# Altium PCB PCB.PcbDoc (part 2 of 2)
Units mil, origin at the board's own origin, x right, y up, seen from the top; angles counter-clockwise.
Board outline 3920 x 1470 mil, 2 copper layers (Top Layer, Bottom Layer), stack 60.433 mil thick; 97 components, 79 nets, 353 pads, 374 vias.
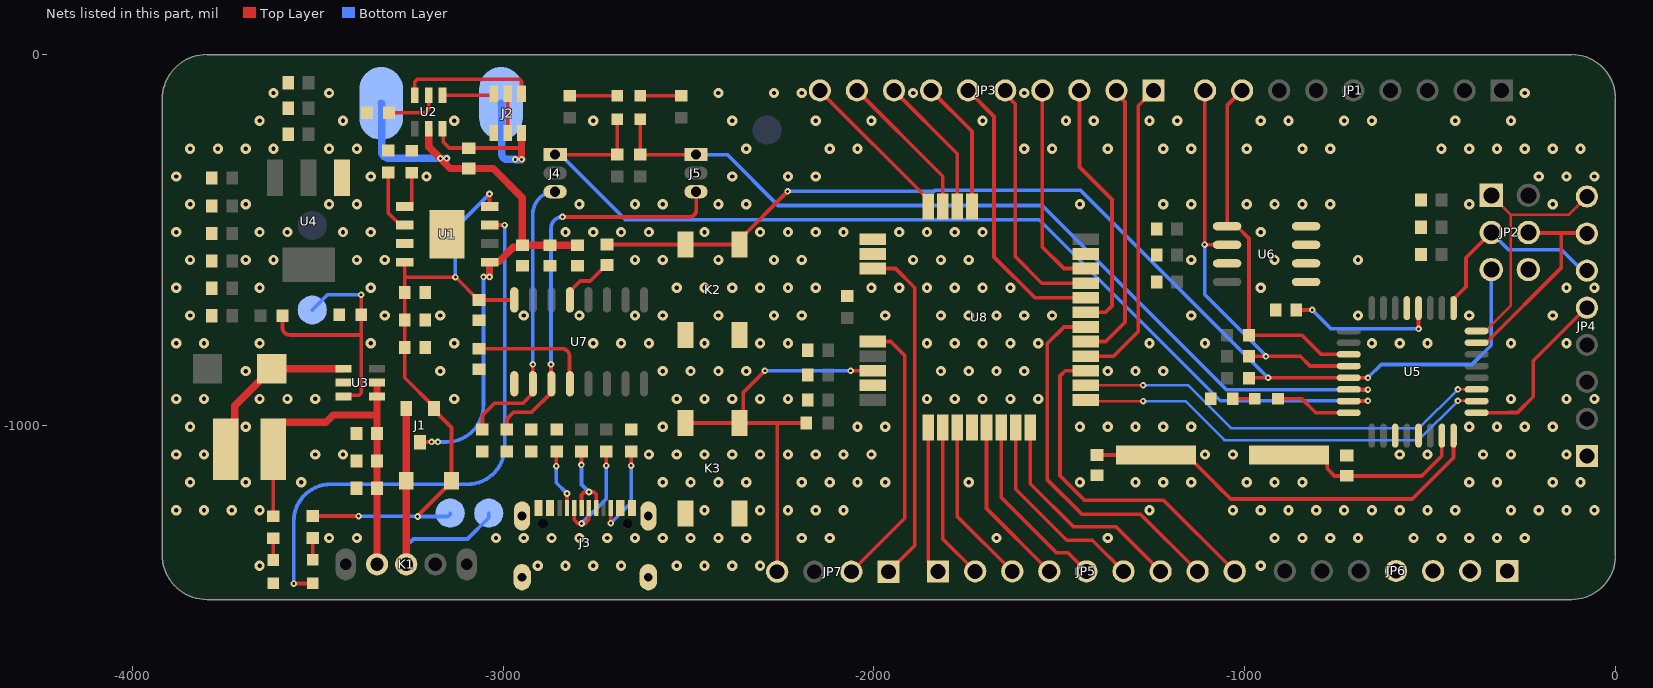
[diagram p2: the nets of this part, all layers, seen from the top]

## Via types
v1: diameter 27.56, hole 11.81, Top Layer to Bottom Layer, tented both sides, 319 vias
v2: diameter 17.72, hole 7.87, Top Layer to Bottom Layer, tented both sides, 55 vias

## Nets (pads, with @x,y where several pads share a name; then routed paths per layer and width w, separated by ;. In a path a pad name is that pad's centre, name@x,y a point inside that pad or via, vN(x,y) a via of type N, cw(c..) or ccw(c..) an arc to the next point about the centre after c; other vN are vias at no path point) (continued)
GND: C1.2 C2.2 C3.2 C4.2 C5.2 C6.2 C8.2 C9.2 C10.2 C11.2 C12.2 C13.2 C14.2 C15.2 C16.2 C17.2 C18.2 C19.2 C20.2 C21.2 C23.2 C24.2 C25.2 C26.2 C27.2 C28.2 C30.2 C31.2 C32.2 C33.2 C34.2 C35.2 D3.1 J2.1 J3.1 J3.12 J3.13 J3.14 JP2.4 JP4.1 JP6.1 JP6.2 JP6.3 JP6.4 K2.1 K2.3 K3.1 K3.3 R2.1 R3.1 R4.1 R5.1 R8.1 R9.2 R10.2 R14.2 R23.1 U1.3 U1.9 U3.2 U4.1 U5.3 U5.5 U5.21 U6.1 U6.2 U6.3 U6.4 U6.7 U7.1 U8.11 U8.17 U8.18 U8.23 U8.28
  other v1: -3657,-1378.95 -2907,-1378.95 -2832,-1378.95 -2757,-1378.95 -2682,-1378.95 -2532,-1378.95 -2457,-1378.95 -2382,-1378.95 -2307,-1378.95 -957,-1378.95 -3469.5,-1303.95 -3394.5,-1303.95 -3019.5,-1303.95 -2944.5,-1303.95 -2869.5,-1303.95 -2794.5,-1303.95 -2719.5,-1303.95 -2644.5,-1303.95 -2569.5,-1303.95 -2494.5,-1303.95 -2419.5,-1303.95 -2344.5,-1303.95 -2194.5,-1303.95 -2119.5,-1303.95 -1669.5,-1303.95 -1369.5,-1303.95 -919.5,-1303.95 -844.5,-1303.95 -769.5,-1303.95 -694.5,-1303.95 -544.5,-1303.95 -469.5,-1303.95 -394.5,-1303.95 -319.5,-1303.95 -244.5,-1303.95 -3882,-1228.95 -3807,-1228.95 -3732,-1228.95 -3657,-1228.95 -2457,-1228.95 -2307,-1228.95 -2232,-1228.95 -2157,-1228.95 -2082,-1228.95 -1257,-1228.95 -1032,-1228.95 -957,-1228.95 -882,-1228.95 -807,-1228.95 -732,-1228.95 -657,-1228.95 -582,-1228.95 -507,-1228.95 -432,-1228.95 -282,-1228.95 -207,-1228.95 -132,-1228.95 -57,-1228.95 -3844.5,-1153.95 -3694.5,-1153.95 -3544.5,-1153.95 -2569.5,-1153.95 -2494.5,-1153.95 -2419.5,-1153.95 -2344.5,-1153.95 -2194.5,-1153.95 -2119.5,-1153.95 -2044.5,-1153.95 -1969.5,-1153.95 -1744.5,-1153.95 -1444.5,-1153.95 -1294.5,-1153.95 -1219.5,-1153.95 -1144.5,-1153.95 -994.5,-1153.95 -919.5,-1153.95 -844.5,-1153.95 -394.5,-1153.95 -319.5,-1153.95 -169.5,-1153.95 -94.5,-1153.95 -3882,-1078.95 -3807,-1078.95 -3507,-1078.95 -3432,-1078.95 -2607,-1078.95 -2532,-1078.95 -2457,-1078.95 -2382,-1078.95 -2307,-1078.95 -2232,-1078.95 -2157,-1078.95 -2082,-1078.95 -2007,-1078.95 -1107,-1078.95 -1032,-1078.95 -582,-1078.95 -507,-1078.95 -357,-1078.95 -282,-1078.95 -132,-1078.95 -3844.5,-1003.95 -3694.5,-1003.95 -2569.5,-1003.95 -2044.5,-1003.95 -1969.5,-1003.95 -1444.5,-1003.95 -1369.5,-1003.95 -1294.5,-1003.95 -1219.5,-1003.95 -1144.5,-1003.95 -394.5,-1003.95 -319.5,-1003.95 -244.5,-1003.95 -169.5,-1003.95 -3882,-928.95 -3807,-928.95 -3657,-928.95 -3582,-928.95 -3507,-928.95 -3132,-928.95 -2532,-928.95 -2457,-928.95 -2382,-928.95 -2307,-928.95 -2232,-928.95 -1857,-928.95 -1782,-928.95 -1707,-928.95 -1632,-928.95 -1557,-928.95 -282,-928.95 -132,-928.95 -57,-928.95 -3694.5,-853.95 -3169.5,-853.95 -2569.5,-853.95 -2494.5,-853.95 -2419.5,-853.95 -2344.5,-853.95 -1819.5,-853.95 -1744.5,-853.95 -1669.5,-853.95 -1594.5,-853.95 -1369.5,-853.95 -1294.5,-853.95 -1219.5,-853.95 -3882,-778.95 -3807,-778.95 -3657,-778.95 -3357,-778.95 -3132,-778.95 -2757,-778.95 -2682,-778.95 -2607,-778.95 -2457,-778.95 -2307,-778.95 -2232,-778.95 -1857,-778.95 -1782,-778.95 -1707,-778.95 -1632,-778.95 -1557,-778.95 -1257,-778.95 -1107,-778.95 -657,-778.95 -582,-778.95 -507,-778.95 -282,-778.95 -132,-778.95 -3844.5,-703.95 -3319.5,-703.95 -3169.5,-703.95 -2944.5,-703.95 -2794.5,-703.95 -2644.5,-703.95 -2569.5,-703.95 -2419.5,-703.95 -2269.5,-703.95 -2194.5,-703.95 -1969.5,-703.95 -1819.5,-703.95 -1744.5,-703.95 -1669.5,-703.95 -1594.5,-703.95 -1519.5,-703.95 -1144.5,-703.95 -694.5,-703.95 -394.5,-703.95 -169.5,-703.95 -3882,-628.95 -3657,-628.95 -3357,-628.95 -2532,-628.95 -2457,-628.95 -2382,-628.95 -2307,-628.95 -2232,-628.95 -2157,-628.95 -2007,-628.95 -1932,-628.95 -1857,-628.95 -1782,-628.95 -1707,-628.95 -1632,-628.95 -957,-628.95 -132,-628.95 -57,-628.95 -3844.5,-553.95 -3694.5,-553.95 -3619.5,-553.95 -3394.5,-553.95 -3319.5,-553.95 -2644.5,-553.95 -2569.5,-553.95 -2419.5,-553.95 -2269.5,-553.95 -2194.5,-553.95 -1894.5,-553.95 -1819.5,-553.95 -1744.5,-553.95 -1144.5,-553.95 -919.5,-553.95 -694.5,-553.95 -3882,-478.95 -3657,-478.95 -3582,-478.95 -3432,-478.95 -3357,-478.95 -2832,-478.95 -2757,-478.95 -2682,-478.95 -2607,-478.95 -2457,-478.95 -2307,-478.95 -2232,-478.95 -2157,-478.95 -2082,-478.95 -1932,-478.95 -1857,-478.95 -1782,-478.95 -1707,-478.95 -957,-478.95 -3844.5,-403.95 -3694.5,-403.95 -3469.5,-403.95 -3394.5,-403.95 -2794.5,-403.95 -2644.5,-403.95 -2569.5,-403.95 -2419.5,-403.95 -2344.5,-403.95 -1444.5,-403.95 -1219.5,-403.95 -1144.5,-403.95 -994.5,-403.95 -919.5,-403.95 -844.5,-403.95 -769.5,-403.95 -394.5,-403.95 -169.5,-403.95 -3882,-328.95 -3357,-328.95 -3207,-328.95 -2382,-328.95 -2232,-328.95 -2157,-328.95 -207,-328.95 -132,-328.95 -57,-328.95 -3844.5,-253.95 -3769.5,-253.95 -3694.5,-253.95 -3619.5,-253.95 -3469.5,-253.95 -3394.5,-253.95 -2344.5,-253.95 -2119.5,-253.95 -2044.5,-253.95 -1594.5,-253.95 -1519.5,-253.95 -1369.5,-253.95 -1219.5,-253.95 -1144.5,-253.95 -994.5,-253.95 -844.5,-253.95 -769.5,-253.95 -469.5,-253.95 -394.5,-253.95 -319.5,-253.95 -244.5,-253.95 -169.5,-253.95 -94.5,-253.95 -3657,-178.95 -3432,-178.95 -3132,-178.95 -2757,-178.95 -2382,-178.95 -2157,-178.95 -2007,-178.95 -1707,-178.95 -1482,-178.95 -1407,-178.95 -1257,-178.95 -1182,-178.95 -957,-178.95 -882,-178.95 -732,-178.95 -657,-178.95 -432,-178.95 -282,-178.95 -3619.5,-103.95 -3469.5,-103.95 -2419.5,-103.95 -2269.5,-103.95 -2194.5,-103.95 -1894.5,-103.95 -1594.5,-103.95 -244.5,-103.95
MISO: JP2.1 JP4.8 U5.16 | length 665.3
  Top Layer w7: U5.16@-374.5,-745.76 -350.88,-745.76 -283,-677.89 -283,-432 ; JP2.1@-335,-380 -283,-432 ; JP4.8@-77,-383 -126,-432 -283,-432
MOSI: JP2.5 JP4.7 U5.15 | length 564.7
  Top Layer w10: U5.15@-374.5,-777.26 -348.88,-777.26 -146,-574.38 -146,-481.5 ; JP2.5@-235,-480 -233.5,-481.5 -146,-481.5 ; JP4.7@-77,-483 -78.5,-481.5 -146,-481.5
NetC7_2: C7.2 J2.3 SP2.1 U2.6 | length 519.2
  Top Layer w10: U2.6@-3163.6,-200.24 -3161.66,-202.17 -3161.66,-236.34 -3145.56,-252.44 C7.2@-3093,-252.44 -2957.44,-252.44 ; v2@-2967.78,-283.28 v2(-2967.5,-283) ; v2@-2950.6,-283 v2(-2950.5,-283) v2@-2950,-283
  Top Layer w20: v2@-2950.6,-283 J2.3@-2950.6,-212.15
  Bottom Layer w20: SP2.1@-3006,-132 cw(c-3006,-134) -3004,-134 -3004,-267 ccw(c-2988,-267) -2988,-283 v2(-2967.5,-283) -2966.5,-284 -2951.5,-284 v2(-2950.5,-283)
NetC20_1: C20.1 C22.2 U5.7 | length 522.2
  Top Layer w10: C22.2@-880.75,-1080 -798.07,-1080 -777.48,-1100.59 -777.48,-1116.8 -757.72,-1136.56 C20.1@-725,-1136.56 -522.56,-1136.56 -468.26,-1082.26 U5.7@-468.26,-1028
NetC21_1: C21.1 C22.1 U5.8 | length 1116.6
  Top Layer w10: C21.1@-1398,-1080 C22.1@-1239.25,-1080 -1156.57,-1080 -1076,-1160.57 -1076,-1161 -1038,-1199 -548,-1199 -436.76,-1087.76 U5.8@-436.76,-1028
NetC23_1: C23.1 U5.20 | length 407.3
  Top Layer w10: C23.1@-861.44,-689 v2(-818,-689) ; U5.20@-531.25,-684 -531.2,-684.06 -531.2,-739.8 v2(-531.14,-739.86)
  Bottom Layer w10: v2(-818,-689) -767.14,-739.86 v2(-531.14,-739.86)
NetC27_1: C27.1 U7.4 | length 330.4
  Top Layer w10: C27.1@-3065,-793.44 -2841.56,-793.44 cw(c-2841.56,-814) -2821,-814 -2821,-887.09 ccw(c-2820,-887.09) U7.4@-2820,-888.09
NetC29_1: C29.1 U7.13 | length 152.7
  Top Layer w10: U7.13@-2820,-661.91 -2820,-638.58 -2792.42,-611 -2765.41,-611 -2721.97,-567.56 C29.1@-2720,-567.56
NetD1_1: D1.1 U1.7 | length 1543.1
  Top Layer w10: v2(-3565,-1427) -3514.46,-1427 ccw(c-3514.46,-1425.94) D1.1@-3513.4,-1425.94 ; U1.7@-3036.75,-460 v2(-2996,-460)
  Bottom Layer w10: v2(-3565,-1427) -3565,-1259 cw(c-3465,-1259) -3465,-1159 -3096,-1159 ccw(c-3096,-1059) -2996,-1059 v2(-2996,-460)
NetD1_2: D1.2 R1.2 | length 58.9
  Top Layer w10: D1.2@-3513.68,-1362.99 R1.2@-3513.68,-1304.12
NetD2_2: D2.2 L1.2 U3.1 | length 462.2
  Top Layer w20: L1.2@-3748.1,-1065 -3723.65,-1040.55 -3723.65,-946.86 D2.2@-3624.38,-847.6 U3.1@-3430.79,-847.6
NetD3_2: D3.2 R7.2 | length 58.9
  Top Layer w10: D3.2@-3620.14,-1363.52 R7.2@-3620.14,-1304.66
NetD5_1: D5.1 R14.1 | length 58.9
  Top Layer w10: R14.1@-1032.07,-928.25 -973.34,-928.25 D5.1@-973.2,-928.38
NetD6_2: D6.2 R16.2 | length 110.3
  Top Layer w10: D6.2@-2630.28,-111.34 R16.2@-2520,-111.34
NetD7_2: D7.2 R17.2 | length 127.3
  Top Layer w10: R17.2@-2820,-111.34 D7.2@-2692.68,-111.34
NetJ2_2: J2.2 J2.5 | length 106.3
  Top Layer w10: J2.2@-2988,-212.15 J2.5@-2988,-105.85
NetJ2_4: J2.4 U2.3 | length 362.5
  Top Layer w10: U2.3@-3238.4,-109.76 -3238.4,-74.4 -3230.4,-66.4 -2956.46,-66.4 -2950.6,-72.26 J2.4@-2950.6,-105.85
NetJ2_6: J2.6 U2.1 | length 139.8
  Top Layer w10: U2.1@-3163.6,-109.76 -3029.32,-109.76 J2.6@-3025.4,-105.85
NetJ3_4: J3.4 R10.1 | length 164.4
  Top Layer w10: v2(-2857,-1110) -2857,-1071.89 R10.1@-2855.98,-1070.88 ; J3.4@-2827.99,-1222.87 v2(-2828,-1184)
  Bottom Layer w10: v2(-2857,-1110) -2857,-1155 v2(-2828,-1184)
NetJ3_5: J3.5 J3.7 R12.1 | length 337.7
  Top Layer w10: J3.5@-2808.31,-1222.87 -2808.31,-1254.69 -2798,-1265 v2(-2788.5,-1265) -2779,-1265 -2768.94,-1254.94 J3.7@-2768.94,-1222.87 ; v2(-2722.03,-1108.85) -2722,-1111 -2721.8,-1110.8 R12.1@-2721.8,-1070.88
  Bottom Layer w10: v2(-2788.5,-1265) -2722.03,-1198.53 v2(-2722.03,-1108.85)
NetJ3_6: J3.6 J3.8 R11.1 | length 234.4
  Top Layer w10: v2(-2789,-1107) -2788.73,-1106.73 R11.1@-2788.73,-1070.88 ; J3.6@-2788.62,-1222.87 -2788.62,-1187.62 -2781,-1180 v2(-2768.5,-1180) -2756,-1180 -2749.26,-1186.74 J3.8@-2749.26,-1222.87
  Bottom Layer w10: v2(-2789,-1107) -2789,-1159.5 v2(-2768.5,-1180)
NetJ3_10: J3.10 R9.1 | length 257.1
  Top Layer w10: v2(-2710,-1264) -2710,-1261 -2709.89,-1260.89 J3.10@-2709.89,-1222.87 ; v2(-2655,-1109) -2655,-1071.01 R9.1@-2654.87,-1070.88
  Bottom Layer w10: v2(-2710,-1264) -2655,-1209 v2(-2655,-1109)
NetR2_2: R2.2 U1.2 | length 166.7
  Top Layer w10: R2.2@-3309.81,-318.44 -3309.81,-427.75 -3277.56,-460 U1.2@-3265.75,-460
NetR4_2: R4.2 U1.1 | length 106
  Top Layer w10: U1.1@-3265.75,-410 -3253.94,-410 -3247.13,-403.19 -3247.13,-397.46 -3247,-397.33 R4.2@-3247,-318.66
NetR5_2: R5.2 U2.2 | length 148.7
  Top Layer w10: R5.2@-3308.34,-157 -3211,-157 -3201,-147 U2.2@-3201,-109.76
NetR6_1: R6.1 R8.2 TP3.1 U3.3 | length 721.6
  Top Layer w10: R6.1@-3595.34,-704.46 -3595.34,-736.66 ccw(c-3575.66,-736.66) -3575.66,-756.34 -3383,-756.34 ; U3.3@-3430.79,-922.4 -3427.59,-919.2 -3388.86,-919.2 -3383,-913.34 -3383,-756.34 ; v2(-3383,-648) R8.2@-3383,-702 -3383,-756.34
  Bottom Layer w10: TP3.1@-3515,-689 -3474,-648 v2(-3383,-648)
PA0: JP5.4 U8.29 | length 458.2
  Top Layer w10: U8.29@-1696.31,-1005.98 -1696.31,-1224.69 JP5.4@-1527,-1394
PA1: JP5.8 U8.6 | length 997.4
  Top Layer w10: U8.6@-1429.09,-734.78 -1487.77,-734.78 -1533,-780 -1533,-1146 -1439,-1240 -1281,-1240 JP5.8@-1127,-1394
PA8: JP7.1 U8.19 | length 929.7
  Top Layer w10: U8.19@-2002.91,-577.3 -1941.7,-577.3 -1890,-629 -1890,-1324 JP7.1@-1961,-1395
PA9: JP7.2 U8.20 | length 744.2
  Top Layer w10: JP7.2@-2061,-1395 -1917,-1251 -1917,-812 -1954.85,-774.15 U8.20@-2002.91,-774.15
PA10: JP5.1 U8.25 | length 399.1
  Top Layer w10: U8.25@-1853.79,-1005.98 -1853.79,-1367.21 JP5.1@-1827,-1394
PA15: JP5.9 U8.3 | length 921.6
  Top Layer w10: U8.3@-1429.09,-852.89 -1483.89,-852.89 -1498,-867 -1498,-1136 -1432,-1202 -1219,-1202 JP5.9@-1027,-1394
PB2: JP5.2 U8.26 | length 424.2
  Top Layer w10: U8.26@-1814.42,-1005.98 -1814.42,-1306.58 JP5.2@-1727,-1394
PB3: JP5.7 U8.32 | length 600.9
  Top Layer w10: U8.32@-1578.2,-1005.98 -1578.2,-1157.8 -1462,-1274 -1347,-1274 JP5.7@-1227,-1394
PB4: JP5.6 U8.31 | length 548.8
  Top Layer w10: U8.31@-1617.57,-1005.98 -1617.57,-1172.43 -1480,-1310 -1411,-1310 JP5.6@-1327,-1394
PB5: JP5.5 U8.30 | length 501.4
  Top Layer w10: U8.30@-1656.94,-1005.98 -1656.94,-1195.06 -1508,-1344 -1477,-1344 JP5.5@-1427,-1394
PB12: JP5.3 U8.27 | length 449.3
  Top Layer w10: U8.27@-1775.05,-1005.98 -1775.05,-1245.95 JP5.3@-1627,-1394
RESET: C29.2 JP2.3 K2.2 K2.4 R18.1 U5.29 | length 2955.8
  Top Layer w10: C29.2@-2720,-512.44 K2.2@-2507.84,-512.44 K2.4@-2362.16,-512.44 -2362.16,-498.66 -2233,-369.5 v2(-2233,-369) ; R18.1@-988.18,-872.78 -987.15,-871.75 v2(-937,-871.75) U5.29@-719.5,-871.75 -719.25,-872 v2(-668,-872)
  Bottom Layer w10: v2(-2233,-369) -1838.33,-369 -1835.33,-366 -1442.75,-366 v2(-937,-871.75) ; v2(-668,-872) -632,-836 -386.8,-836 -335,-784.2 JP2.3@-335,-580
RESET_RAK3172: JP7.4 K3.2 K3.4 R24.1 U8.22 | length 1172.7
  Top Layer w10: K3.2@-2497.84,-994 K3.4@-2352.16,-994 ; v2(-2294,-853) -2352.16,-911.16 K3.4@-2352.16,-994 ; JP7.4@-2261,-1395 -2261,-995 -2260,-994 ; R24.1@-2182.76,-994 -2260,-994 ; v2(-2063,-853) -2062.89,-852.89 U8.22@-2002.91,-852.89 ; K3.4@-2352.16,-994 -2260,-994
  Bottom Layer w10: v2(-2294,-853) v2(-2063,-853)
RESET_TFT: JP4.5 U5.9 | length 471.6
  Top Layer w10: U5.9@-374.5,-966.24 -289.98,-966.24 -289.25,-965.5 -264.5,-965.5 -221.84,-922.84 -221.84,-825.84 -79,-683 JP4.5@-77,-683
RXD_HV: J5.3 R21.2 U7.3 | length 1091.1
  Top Layer w10: R21.2@-2990,-1011.34 -2990,-983 -2972,-965 -2923.58,-965 -2870,-911.42 U7.3@-2870,-888.09 cw(c-2870,-887.09) -2871,-887.09 v2(-2871,-836) ; v2(-2840,-438) -2498,-438 ccw(c-2498,-419) -2479,-419 -2479,-371 ccw(c-2480,-371) J5.3@-2480,-370
  Bottom Layer w10: v2(-2871,-836) -2871,-469 cw(c-2840,-469) v2(-2840,-438)
RXD_LV: D7.1 J4.1 R20.2 U5.31 | length 2782.1
  Top Layer w10: J4.1@-2860,-270 R20.2@-2692.41,-270 D7.1@-2692.41,-174.29 ; U5.31@-719.5,-934.74 -719.13,-934.37 -668.37,-934.37 v2(-668,-934)
  Bottom Layer w10: J4.1@-2860,-270 -2846.22,-270 -2670.22,-446 -1554,-446 -1066,-934 v2(-668,-934)
RXD_RAK3172: U5.10 U8.1 | length 1143.7
  Top Layer w7: U8.1@-1429.09,-931.62 -1425.72,-935 v2(-1274,-935) ; v2(-425,-934) -424.63,-934.37 -374.87,-934.37 U5.10@-374.5,-934.74
  Bottom Layer w7: v2(-1274,-935) -1159.61,-935 -1054.61,-1040 -531,-1040 v2(-425,-934)
S1_MISO_RAK: JP3.8 U8.14 | length 383.8
  Top Layer w10: JP3.8@-1945.91,-97.02 -1775.06,-267.88 U8.14@-1775.06,-410.02
S1_MOSI_RAK: JP3.7 U8.13 | length 358.7
  Top Layer w10: JP3.7@-1845.91,-97.02 -1735.69,-207.25 U8.13@-1735.69,-410.02
S1_NSS_RAK: JP3.10 U8.16 | length 434
  Top Layer w10: JP3.10@-2145.91,-97.02 -2145.91,-98.22 -1853.8,-390.34 U8.16@-1853.8,-410.02
S1_SCK_RAK: JP3.9 U8.15 | length 408.9
  Top Layer w10: JP3.9@-2045.91,-97.02 -1814.43,-328.51 U8.15@-1814.43,-410.02
SCK: JP2.2 JP4.6 U5.17 | length 546.8
  Top Layer w10: U5.17@-436.76,-684 -436.76,-660.38 -403,-626.61 -403,-548 JP2.2@-335,-480
  Bottom Layer w10: JP2.2@-335,-480 -288,-527 -145,-527 -89,-583 JP4.6@-77,-583
SCL: JP1.9 R13.2 U5.28 U6.6 | length 1127.1
  Top Layer w10: JP1.9@-1107,-97 -1107.5,-97.5 -1107.5,-512.5 v2(-1108,-513) -1107.59,-513.41 U6.6@-1047.5,-513.41 ; R13.2@-988.18,-813.78 -850.22,-813.78 -823.75,-840.25 U5.28@-719.5,-840.25
  Bottom Layer w10: v2(-1108,-513) -1108,-647 -942.76,-812.24 v2(-942.76,-814.27) ; JP1.9@-1107.5,-97.5 JP1.9@-1107,-97
SCL_RAK: JP3.5 U8.9 | length 678.7
  Top Layer w10: JP3.5@-1645.91,-97.02 -1645.91,-106.72 -1619,-133.64 -1619,-545 -1547.34,-616.66 U8.9@-1429.09,-616.66
SDA: JP1.8 R15.2 U5.27 U6.5 | length 1006.8
  Top Layer w10: JP1.8@-1007,-97 -1047.5,-137.5 U6.5@-1047.5,-463.41 -1021.59,-463.41 -988.73,-496.27 -988.73,-756.68 R15.2@-988.18,-757.23 -845.77,-757.23 -794.24,-808.76 U5.27@-719.5,-808.76
SDA_RAK: JP3.4 U8.10 | length 563
  Top Layer w10: JP3.4@-1545.91,-97.02 -1545.91,-519.09 -1487.7,-577.3 U8.10@-1429.09,-577.3
SWCLK_RAK: JP3.6 U8.8 | length 770.4
  Top Layer w10: JP3.6@-1745.91,-97.02 -1676,-166.94 -1676,-546 -1565.97,-656.03 U8.8@-1429.09,-656.03
SWDIO_RAK: JP3.3 U8.7 | length 695.7
  Top Layer w10: JP3.3@-1445.91,-97.02 -1445.91,-303.09 -1358,-391 -1358,-678 -1375.4,-695.41 U8.7@-1429.09,-695.41
"TOGGLE LED": D5.2 U5.32 | length 206.5
  Top Layer w10: D5.2@-910.25,-928.11 -846.89,-928.11 -808.76,-966.24 U5.32@-719.5,-966.24
TXD_HV: J4.3 R19.2 U7.2 | length 776.8
  Top Layer w10: R19.2@-3056,-1011.34 -3056,-973 -3024,-941 -2947.42,-941 -2920,-913.58 U7.2@-2920,-888.09 v2(-2920,-836)
  Bottom Layer w10: v2(-2920,-836) -2920,-430 cw(c-2860,-430) J4.3@-2860,-370
TXD_LV: D6.1 J5.1 R22.2 U5.30 | length 2372.1
  Top Layer w10: D6.1@-2630,-174.29 R22.2@-2630,-270 J5.1@-2480,-270 ; U5.30@-719.5,-903.24 -719.12,-903.62 -668.38,-903.62 v2(-668,-904)
  Bottom Layer w10: J5.1@-2480,-270 -2396,-270 -2259,-407 -1546,-407 -1049,-904 v2(-668,-904)
TXD_RAK3172: U5.11 U8.2 | length 1146.3
  Top Layer w7: U8.2@-1429.09,-892.26 -1274.26,-892.26 v2(-1274,-892) ; v2(-425,-903) -424.88,-903.12 -374.62,-903.12 U5.11@-374.5,-903.24
  Bottom Layer w7: v2(-1274,-892) -1153,-892 -1037,-1008 -530,-1008 v2(-425,-903)
U1_TXD_RAK: JP3.1 U8.4 | length 836.6
  Top Layer w10: U8.4@-1429.09,-813.51 -1353.52,-813.51 -1287,-747 -1287,-138.11 JP3.1@-1245.91,-97.02
U2_RXD_RAK: JP3.2 U8.5 | length 762.2
  Top Layer w10: U8.5@-1429.09,-774.14 -1375.15,-774.14 -1323,-722 -1323,-127.8 -1345.91,-104.89 JP3.2@-1345.91,-97.02
V-BAT: C4.1 C5.1 C6.1 C7.1 J1.3 SP1.1 U1.5 U2.5 | length 1673.3
  Top Layer w10: J1.3@-3224.17,-1045.28 -3193.28,-1045.28 v2(-3193,-1045) ; v2@-3169.75,-280.25 v2(-3169.5,-280)
  Top Layer w20: U2.5@-3201,-200.24 -3201,-249 -3169.75,-280.25 -3142.44,-307.56 C7.1@-3093,-307.56 -3026.44,-307.56 -2948.12,-385.88 C4.1@-2948.12,-514.25 ; v2(-3037,-600) -3037,-560.25 -3034.94,-558.19 -3011.19,-558.19 -2973,-520 -2953.87,-520 C4.1@-2948.12,-514.25 ; C6.1@-2800.07,-514.25 C5.1@-2874.21,-514.25 C4.1@-2948.12,-514.25
  Bottom Layer w10: v2(-3193,-1045) -3192,-1046 -3177,-1046 v2(-3176,-1045) -3153,-1045 ccw(c-3153,-945) -3053,-945 v2(-3053,-600)
  Bottom Layer w20: SP1.1@-3329,-132 cw(c-3329,-133) -3328,-133 -3328,-260 ccw(c-3308,-260) -3308,-280 v2(-3169.5,-280) -3168.5,-281 -3153.5,-281 v2(-3152.5,-280)
V-BUCKBOOST: C11.1 C12.1 C13.1 K1.1 L1.1 R7.1 U3.4 U3.5 | length 1016.8
  Top Layer w10: R7.1@-3620.14,-1245.34 L1.1@-3620.14,-1065
  Top Layer w20: L1.1@-3620.14,-1065 -3620.14,-1016.77 -3595.69,-992.32 -3478.03,-992.32 -3457.98,-972.28 -3340.31,-972.28 ; K1.1@-3340.31,-1375 C13.1@-3340.31,-1169.97 C12.1@-3340.31,-1096.06 C11.1@-3340.31,-1022.15 -3340.31,-972.28 ; U3.5@-3340.31,-885 U3.4@-3340.31,-922.4 -3340.31,-972.28
V-BUS: C1.1 C2.1 C3.1 C28.1 D4.2 J1.1 J3.2 J3.11 R1.1 R3.2 R19.1 R21.1 TP5.1 U1.4 U1.8 U7.16 | length 1769.1
  Top Layer w10: R1.1@-3513.68,-1244.8 -3398.2,-1244.8 -3398,-1245 v2(-3390,-1245) ; U1.4@-3265.75,-560 -3265.75,-601.01 ; v2(-3231,-1246) -3231,-1244.78 -3139.53,-1153.31 D4.2@-3139.53,-1149.37 -3139.53,-1005.9 -3186.77,-958.66 J1.1@-3186.77,-954.72 -3186.77,-950.79 -3265.75,-871.81 C3.1@-3265.75,-789.85 C2.1@-3265.75,-715.94 C1.1@-3265.75,-642.03 -3265.75,-601.01 ; v2@-3128.95,-601.01 -3265.75,-601.01 ; v2@-3127.86,-601.01 -3066.97,-661.91 C28.1@-3065,-661.91 U7.16@-2970,-661.91 ; v2(-3037,-376) -3037,-379 -3036.75,-379.25 U1.8@-3036.75,-410
  Bottom Layer w10: v2(-3390,-1245) -3389.5,-1245.5 -3231.5,-1245.5 v2(-3231,-1246) -3152,-1246 ccw(c-3152,-1237) TP5.1@-3143,-1237 ; v2(-3128.95,-600.57) -3128.95,-467.95 v2(-3037,-376)
VCC: D4.1 J1.2 K1.2 TP1.1 | length 735.7
  Top Layer w20: K1.2@-3261.57,-1375 D4.1@-3261.57,-1149.37 J1.2@-3261.57,-954.72
  Bottom Layer w10: K1.2@-3261.57,-1375 -3261.57,-1326.57 -3241.68,-1306.68 -3096.17,-1306.68 -3039,-1249.51 TP1.1@-3039,-1237
pads on no net: J3. J3.3 J3.9 K1.3 K1.4 K1.5 U1.6 U2.4 U3.6 U4.4 U5.12 U5.13 U7.7 U7.8 U7.9 U7.10 U7.11 U7.12 U7.14 U7.15 U8.12

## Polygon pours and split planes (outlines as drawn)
GND on Top Layer "GND_L01_P061" (solid, pour order 61): -3920,-1348.7 ccw(c-3798.7,-1348.7) -3798.7,-1470 -118.5,-1470 ccw(c-118.5,-1351.5) 0,-1351.5 0,-118.5 ccw(c-118.5,-118.5) -118.5,0 -3798.44,0 ccw(c-3798.44,-121.56) -3920,-121.56
GND on Top Layer "NONET_L01_P027" (solid, shelved, pour order 27): -4160,-1347.21 -4160,-206.17 cw(c-4042.83,-206.17) -4042.83,-89 -342.48,-89 cw(c-342.48,-208.48) -223,-208.48 -223,-1348.74 cw(c-341.21,-1348.74) -341.21,-1466.95 -4040.26,-1466.95 cw(c-4040.26,-1347.21)
GND on Bottom Layer "GND_L02_P060" (solid, pour order 60): -3920,-1348.7 ccw(c-3798.7,-1348.7) -3798.7,-1470 -118.5,-1470 ccw(c-118.5,-1351.5) 0,-1351.5 0,-118.5 ccw(c-118.5,-118.5) -118.5,0 -3798.44,0 ccw(c-3798.44,-121.56) -3920,-121.56

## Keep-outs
Keep-Out Layer:
  circle w10: c-118.11,-1351.89 r62.99
  circle w10: c-118.11,-118.11 r62.99
  circle w10: c-3801.89,-118.11 r62.99
  circle w10: c-3801.89,-1351.89 r62.99
  pour cut-out: -220.47,-118.11 ccw(c-118.11,-118.11) -118.11,-220.47 ccw(c-118.11,-118.11) -15.75,-118.11 ccw(c-118.11,-118.11) -118.11,-15.75 ccw(c-118.11,-118.11)
  pour cut-out: -3801.89,-220.47 cw(c-3801.89,-118.11) -3904.25,-118.11 cw(c-3801.89,-118.11) -3801.89,-15.75 cw(c-3801.89,-118.11) -3699.53,-118.11 cw(c-3801.89,-118.11)
  pour cut-out: -3904.25,-1351.89 ccw(c-3801.89,-1351.89) -3801.89,-1454.25 ccw(c-3801.89,-1351.89) -3699.53,-1351.89 ccw(c-3801.89,-1351.89) -3801.89,-1249.53 ccw(c-3801.89,-1351.89)
  pour cut-out: -220.47,-1351.89 ccw(c-118.11,-1351.89) -118.11,-1454.25 ccw(c-118.11,-1351.89) -15.75,-1351.89 ccw(c-118.11,-1351.89) -118.11,-1249.53 ccw(c-118.11,-1351.89)
  lines w10: -3920,-1348.7 ccw(c-3798.7,-1348.7) -3798.7,-1470 -229,-1470 -118.5,-1470 ccw(c-118.5,-1351.5) 0,-1351.5 0,-118.5 ccw(c-118.5,-118.5) -118.5,0 -3798.44,0 ccw(c-3798.44,-121.56) -3920,-121.56 -3920,-1348.7

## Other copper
Top Layer:
  region net +3.3: -1190,-1166.5 -1190,-1149.5 cw(c-1181,-1149.5) -1181,-1140.5 -1180,-1140.5 cw(c-1180,-1148.5) -1172,-1148.5 -1172,-1166.5 cw(c-1181,-1166.5) -1181,-1175.5 cw(c-1181,-1166.5)
  region net +3.3: -1192,-1016.5 -1192,-999.5 cw(c-1183,-999.5) -1183,-990.5 -1182,-990.5 cw(c-1182,-998.5) -1174,-998.5 -1174,-1016.5 cw(c-1183,-1016.5) -1183,-1025.5 cw(c-1183,-1016.5)
  region net +3.3: -476.5,-292 -459.5,-292 cw(c-459.5,-301) -450.5,-301 -450.5,-302 cw(c-458.5,-302) -458.5,-310 -476.5,-310 cw(c-476.5,-301) -485.5,-301 cw(c-476.5,-301)
  region net +3.3: -1190.94,-292 -1173.94,-292 cw(c-1173.94,-301) -1164.94,-301 -1164.94,-302 cw(c-1172.94,-302) -1172.94,-310 -1190.94,-310 cw(c-1190.94,-301) -1199.94,-301 cw(c-1190.94,-301)
  region net +3.3: -2124.5,-293 -2107.5,-293 cw(c-2107.5,-302) -2098.5,-302 -2098.5,-303 cw(c-2106.5,-303) -2106.5,-311 -2124.5,-311 cw(c-2124.5,-302) -2133.5,-302 cw(c-2124.5,-302)
  region net V-BAT: -3169.5,-271 -3152.5,-271 cw(c-3152.5,-280) -3143.5,-280 -3143.5,-281 cw(c-3151.5,-281) -3151.5,-289 -3169.5,-289 cw(c-3169.5,-280) -3178.5,-280 cw(c-3169.5,-280)
  region net NetC7_2: -2967.5,-274 -2950.5,-274 cw(c-2950.5,-283) -2941.5,-283 -2941.5,-284 cw(c-2949.5,-284) -2949.5,-292 -2967.5,-292 cw(c-2967.5,-283) -2976.5,-283 cw(c-2967.5,-283)
  region net V-BAT: -3054,-591 -3037,-591 cw(c-3037,-600) -3028,-600 -3028,-601 cw(c-3036,-601) -3036,-609 -3054,-609 cw(c-3054,-600) -3063,-600 cw(c-3054,-600)
  region net V-BAT: -3193,-1036 -3176,-1036 cw(c-3176,-1045) -3167,-1045 -3167,-1046 cw(c-3175,-1046) -3175,-1054 -3193,-1054 cw(c-3193,-1045) -3202,-1045 cw(c-3193,-1045)
  region net V-BUS: -3159.21,-1172.39 -2902.61,-1172.39 -2885,-1190 -2885.08,-1190.08 -2885.08,-1244.52 -2861.46,-1244.52 -2861.46,-1189.46 -2838,-1166 -2718,-1166 -2696,-1188 -2696.1,-1188.1 -2696.1,-1244.52 -2672.48,-1244.52 -2673,-1244 -2673,-1167 -2704,-1136 -2879,-1136 -2907.27,-1107.73 -2907.27,-1054.58 -3071.75,-1054.58 -3072.73,-1055.57 -3072,-1056.3 -3072,-1113 -3084.75,-1125.75 -3159.21,-1125.75
Bottom Layer:
  pour cut-out: -644.14,-981.52 -555.2,-892.58 -555.2,-892.18 -440.31,-892.18 -437.59,-894.9 -437.59,-898.97 -438.86,-900.24 -438.86,-906.04 -533.17,-1000.35 -653.03,-1000.35 -653.03,-996.35 -654.02,-995.35 -644.14,-985.47
  region net +3.3: -1190,-1166.5 -1190,-1149.5 cw(c-1181,-1149.5) -1181,-1140.5 -1180,-1140.5 cw(c-1180,-1148.5) -1172,-1148.5 -1172,-1166.5 cw(c-1181,-1166.5) -1181,-1175.5 cw(c-1181,-1166.5)
  region net +3.3: -1192,-1016.5 -1192,-999.5 cw(c-1183,-999.5) -1183,-990.5 -1182,-990.5 cw(c-1182,-998.5) -1174,-998.5 -1174,-1016.5 cw(c-1183,-1016.5) -1183,-1025.5 cw(c-1183,-1016.5)
  region net +3.3: -476.5,-292 -459.5,-292 cw(c-459.5,-301) -450.5,-301 -450.5,-302 cw(c-458.5,-302) -458.5,-310 -476.5,-310 cw(c-476.5,-301) -485.5,-301 cw(c-476.5,-301)
  region net +3.3: -1190.94,-292 -1173.94,-292 cw(c-1173.94,-301) -1164.94,-301 -1164.94,-302 cw(c-1172.94,-302) -1172.94,-310 -1190.94,-310 cw(c-1190.94,-301) -1199.94,-301 cw(c-1190.94,-301)
  region net +3.3: -2124.5,-293 -2107.5,-293 cw(c-2107.5,-302) -2098.5,-302 -2098.5,-303 cw(c-2106.5,-303) -2106.5,-311 -2124.5,-311 cw(c-2124.5,-302) -2133.5,-302 cw(c-2124.5,-302)
  region net V-BAT: -3169.5,-271 -3152.5,-271 cw(c-3152.5,-280) -3143.5,-280 -3143.5,-281 cw(c-3151.5,-281) -3151.5,-289 -3169.5,-289 cw(c-3169.5,-280) -3178.5,-280 cw(c-3169.5,-280)
  region net NetC7_2: -2967.5,-274 -2950.5,-274 cw(c-2950.5,-283) -2941.5,-283 -2941.5,-284 cw(c-2949.5,-284) -2949.5,-292 -2967.5,-292 cw(c-2967.5,-283) -2976.5,-283 cw(c-2967.5,-283)
  region net V-BAT: -3054,-591 -3037,-591 cw(c-3037,-600) -3028,-600 -3028,-601 cw(c-3036,-601) -3036,-609 -3054,-609 cw(c-3054,-600) -3063,-600 cw(c-3054,-600)
  region net V-BAT: -3193,-1036 -3176,-1036 cw(c-3176,-1045) -3167,-1045 -3167,-1046 cw(c-3175,-1046) -3175,-1054 -3193,-1054 cw(c-3193,-1045) -3202,-1045 cw(c-3193,-1045)

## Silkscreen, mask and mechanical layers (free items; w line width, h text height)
Top Overlay:
  text "A2" at -886.23,-223.97 h40 r90
  text "A3" at -786.23,-223.97 h40 r90
  text "A4" at -686.23,-223.97 h40 r90
  text "A5" at -586.23,-223.97 h40 r90
  text "A6" at -486.23,-223.97 h40 r90
  text "A7" at -386.23,-223.97 h40 r90
  text "SCL" at -1088.31,-243.97 h40 r90
  text "SDA" at -987.31,-248.97 h40 r90
  text "D10" at -286.23,-259.52 h40 r90
  text "PA4" at -2126.23,-288.08 h40 r90
  text "PA5" at -2026.23,-288.08 h40 r90
  text "PA6" at -1926.23,-288.08 h40 r90
  text "PA7" at -1826.23,-288.08 h40 r90
  text "PA14" at -1726.23,-288.08 h40 r90
  text "PA12" at -1626.23,-288.08 h40 r90
  text "PA11" at -1526.23,-288.08 h40 r90
  text "PA13" at -1426.23,-288.08 h40 r90
  text "PA7" at -1326.23,-288.08 h40 r90
  text "PA6" at -1226.23,-288.08 h40 r90
  text "+3.3" at -1472.18,-687.09 h40
  text "ICSP" at -336.65,-702.98 h40
  text "RESET ATM" at -2277.48,-741.53 h40 r90
  text "SDA" at -1476.37,-787.09 h40
  text "SCL" at -1472.18,-887.09 h40
  text "GND" at -1483.99,-987.09 h40
  text "SPI_TFT" at -151.5,-1070.01 h40 r90
  text "RESET RAK" at -2277.48,-1218.06 h40 r90
  text "PA10" at -1807.54,-1319.02 h40 r90
  text "PB2" at -1700.54,-1319.02 h40 r90
  text "PA12" at -1600.54,-1319.02 h40 r90
  text "PA0" at -1500.54,-1319.02 h40 r90
  text "PB5" at -1400.54,-1319.02 h40 r90
  text "PB4" at -1300.54,-1319.02 h40 r90
  text "PB3" at -1200.54,-1319.02 h40 r90
  text "PA1" at -1100.54,-1319.02 h40 r90
  text "PA15" at -1000.54,-1319.02 h40 r90
  text "+3.3V" at -874.31,-1319.02 h40 r90
  text "+3.3V" at -772.31,-1319.02 h40 r90
  text "+3.3V" at -672.31,-1319.02 h40 r90
  text "GND" at -572.31,-1319.02 h40 r90
  text "GND" at -472.31,-1319.02 h40 r90
  text "GND" at -373.31,-1319.02 h40 r90
  text "GND" at -273.31,-1319.02 h40 r90
  text "PA8" at -2246.07,-1331.53 h40 r90
  text "PA9" at -2146.07,-1331.53 h40 r90
  text "BOOT" at -2046.07,-1331.53 h40 r90
  text "RESET" at -1946.07,-1331.53 h40 r90
Bottom Overlay:
  lines w10: -190,-1156 -190,-682 -144,-636 -144,-328 ; -813.49,-630 -813.49,-330 -185,-330 -185,-630 -813.49,-630
  text "BAT -" at -3289.56,-259.11 h100 r90
  text "BAT +" at -2962.56,-259.11 h100 r90
  text "+3.3V" at -2258,-262 h60 r90
  text "MISO" at -615,-454 h60
  text "+3.3V" at -435,-454 h60
  text "+5V" at -3575,-492 h60
  text "SCK" at -615,-514 h60
  text "MOSI" at -435,-514 h60
  text "RESET" at -615,-574 h60
  text "GND" at -435,-574 h60
  text "FB" at -3575,-719 h60
  text "MISO" at -202,-740 h60
  text "MOSI" at -202,-800 h60
  text "SCK" at -202,-860 h60
  text "RESET" at -202,-920 h60
  text "DC" at -202,-980 h60
  text "V BUS" at -3111,-988 h60 r90
  text "CS" at -202,-1040 h60
  text "VCC" at -3010,-1053 h60 r90
  text "+3.3V" at -202,-1100 h60
  text "GND" at -202,-1160 h60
